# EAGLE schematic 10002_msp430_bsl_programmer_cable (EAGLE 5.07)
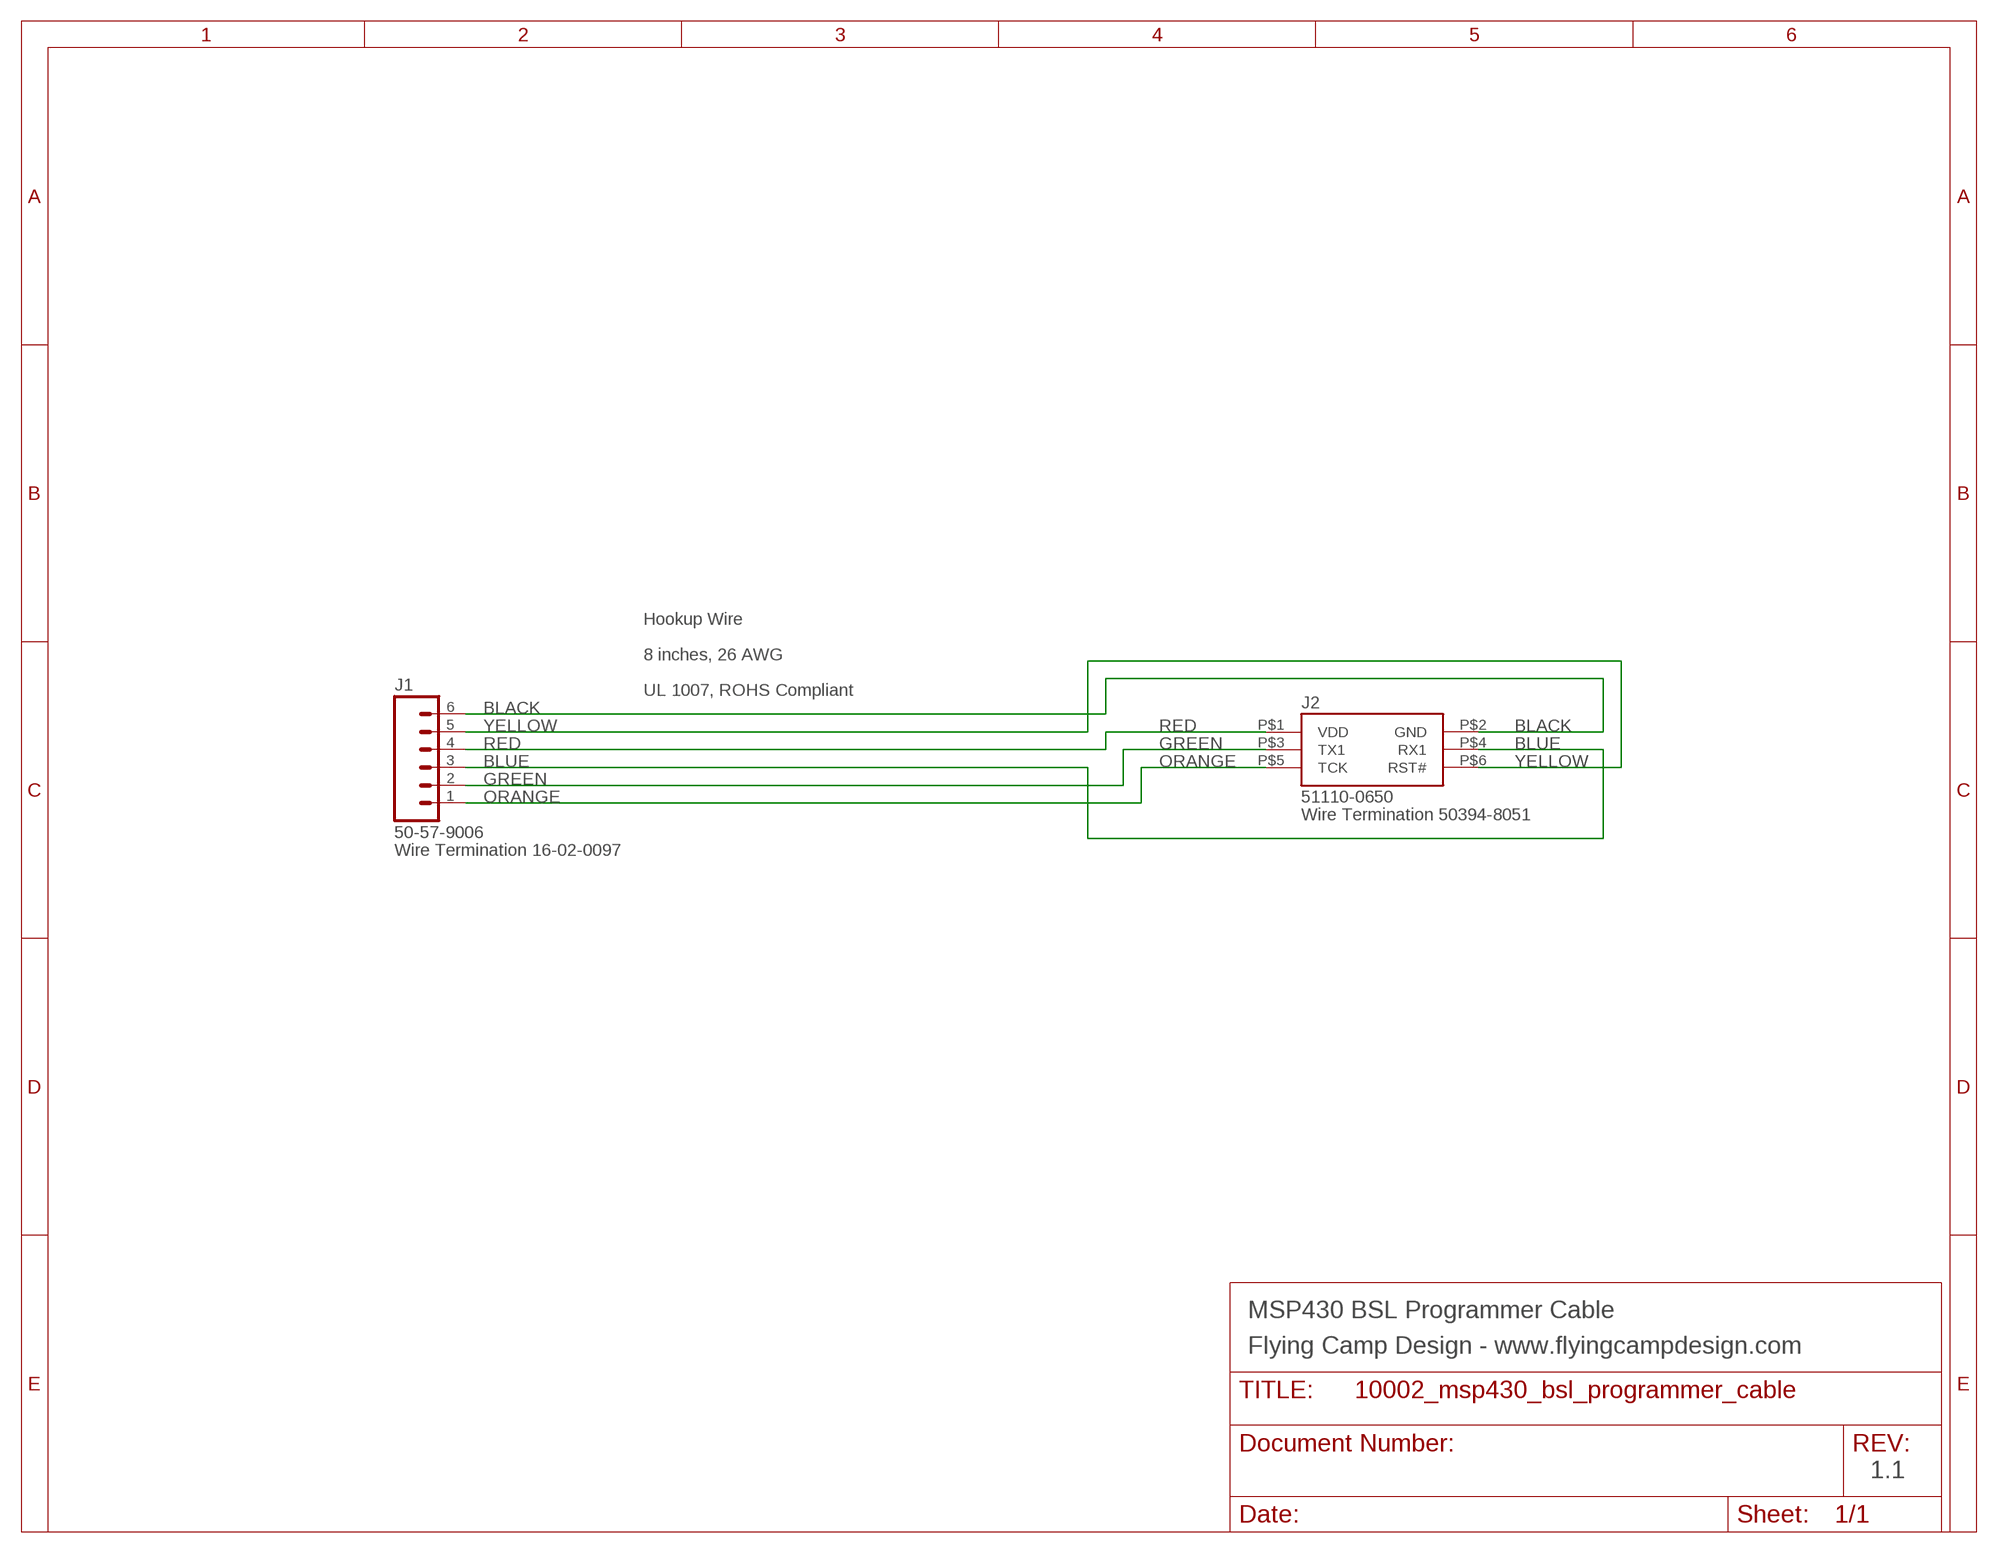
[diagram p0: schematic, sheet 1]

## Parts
J1  50-57-9006  [50-57-9006]
J2  51110-0650  EPIC-PROG-PORT  [HEADER2X3X2MM]

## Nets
BLACK: J1.6 J2.P$2(GND)
BLUE: J1.3 J2.P$4(RX1)
GREEN: J1.2 J2.P$3(TX1)
ORANGE: J1.1 J2.P$5(TCK)
RED: J1.4 J2.P$1(VDD)
YELLOW: J1.5 J2.P$6(RST#)

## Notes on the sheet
- Hookup Wire
- 8 inches, 26 AWG
- UL 1007, ROHS Compliant
- Wire Termination 50394-8051
- Wire Termination 16-02-0097
- MSP430 BSL Programmer Cable
- Flying Camp Design - www.flyingcampdesign.com
- 1.1

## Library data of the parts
J1 = flying_camp_design:50-57-9006
J2 = berkeley-epic:EPIC-PROG-PORT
